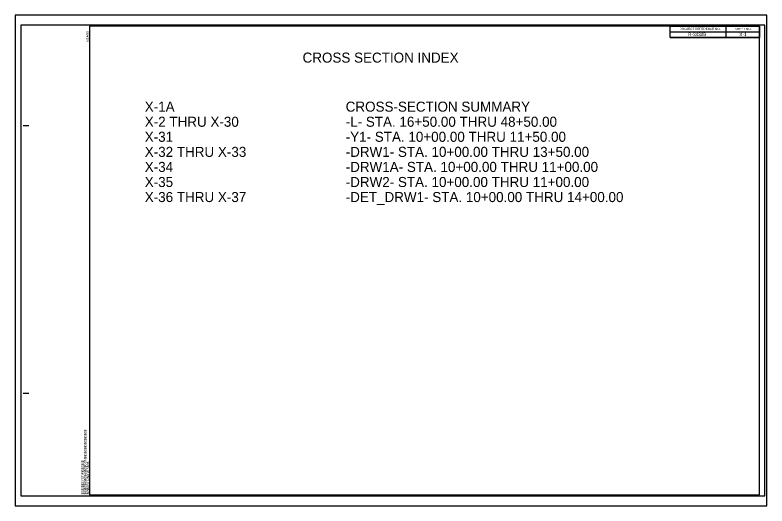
# Model space of a CAD drawing. Extents: x 1726012 to 1727696, y 451844 to 452944.
import ezdxf

# ---------------------------------------------------------------- set-up
doc = ezdxf.new("R2010")
doc.units = 0
for name, color, linetype in [('Prop XS Station Labels', 7, 'Continuous'), ('Sheet Border Standard 30in CELL', 7, 'Continuous'), ('Sheet Cutting Line CELL', 7, 'Continuous'), ('Sheet Data Field CELL', 7, 'Continuous'), ('Sheet Plot Border Inside CELL', 7, 'Continuous'), ('Sheet Plot Border Outside CELL', 7, 'Continuous')]:
    doc.layers.add(name, color=color, linetype=linetype)

msp = doc.modelspace()

# ---------------------------------------------------------------- linework, layer by layer
at = {"layer": 'Sheet Border Standard 30in CELL'}
for p, q in [((1726179.6, 452919.3), (1726179.6, 452919.3)), ((1727603.6, 452919.2), (1727603.6, 452894.2)), ((1727478.5, 452906.7), (1727678.6, 452906.7)), ((1727478.5, 452894.2), (1727678.6, 452894.2)), ((1727478.5, 452894.2), (1727678.6, 452894.2)), ((1726030.1, 452696.8), (1726042.6, 452696.8)), ((1726030.1, 452096.8), (1726042.6, 452096.8))]:
    msp.add_line(p, q, dxfattribs=at)
for points in [[(1727678.6, 452919.3), (1726178.6, 452919.3), (1726178.6, 451869.3), (1727678.6, 451869.3)], [(1727478.5, 452919.3), (1727678.6, 452919.3), (1727678.6, 452894.2), (1727478.5, 452894.2)]]:
    msp.add_lwpolyline(points, close=True, dxfattribs=at)
at = {"layer": 'Sheet Cutting Line CELL'}
for p, q in [((1727695.6, 452944.3), (1726011.6, 452944.3)), ((1726011.6, 452944.3), (1726011.6, 451844.3)), ((1726011.6, 451844.3), (1727695.6, 451844.3))]:
    msp.add_line(p, q, dxfattribs=at)
at = {"layer": 'Sheet Plot Border Inside CELL'}
msp.add_lwpolyline([(1727691.1, 452921.8), (1726024.6, 452921.8), (1726024.6, 451866.7), (1727691.1, 451866.7)], close=True, dxfattribs=at)
at = {"layer": 'Sheet Plot Border Outside CELL'}
msp.add_lwpolyline([(1727695.6, 452944.3), (1726011.6, 452944.3), (1726011.6, 451844.3), (1727695.6, 451844.3)], close=True, dxfattribs=at)

# ---------------------------------------------------------------- texts
at = {"layer": 'Prop XS Station Labels'}
for s, p in [('CROSS SECTION INDEX', (1726655.6, 452837.6)), ('X-1A', (1726302.1, 452727.7)), ('CROSS-SECTION SUMMARY', (1726752.1, 452727.7)), ('X-2 THRU X-30', (1726302.1, 452693.9)), ('-L- STA. 16+50.00 THRU 48+50.00', (1726752.1, 452693.9)), ('X-31', (1726302.1, 452660.2)), ('-Y1- STA. 10+00.00 THRU 11+50.00', (1726752.1, 452660.2)), ('X-32 THRU X-33', (1726302.1, 452626.4)), ('-DRW1- STA. 10+00.00 THRU 13+50.00', (1726752.1, 452626.4)), ('X-34', (1726302.1, 452592.7)), ('-DRW1A- STA. 10+00.00 THRU 11+00.00', (1726752.1, 452592.7)), ('X-35', (1726302.1, 452558.9)), ('-DRW2- STA. 10+00.00 THRU 11+00.00', (1726752.1, 452558.9)), ('X-36 THRU X-37', (1726302.1, 452525.2)), ('-DET_DRW1- STA. 10+00.00 THRU 14+00.00', (1726752.1, 452525.2))]:
    msp.add_text(s, height=22.5, dxfattribs=at).set_placement(p)
at = {"layer": 'Sheet Border Standard 30in CELL'}
for s, p in [('PROJECT REFERENCE NO.', (1727500.7, 452910.6)), ('SHEET NO.', (1727623.9, 452910.5))]:
    msp.add_text(s, height=5, dxfattribs=at).set_placement(p)
for s, p in [('5/14/99', (1726176.3, 452884.1)), ('$$$$$$$$$$$$$$$$DGN$$$$$$$$$$$$$$$$', (1726171.4, 451870.1)), ('$$$$$$SYSTIME$$$$$', (1726165.4, 451870.3)), ('$$$$USERNAME$$$$', (1726177.7, 451870.2))]:
    msp.add_text(s, height=5.25, rotation=90, dxfattribs=at).set_placement(p)
at = {"layer": 'Sheet Data Field CELL'}
for s, p in [('R-3430B', (1727519.1, 452897)), ('X-1', (1727633.7, 452897))]:
    msp.add_text(s, height=7.5, dxfattribs=at).set_placement(p)

doc.saveas('drawing.dxf')
